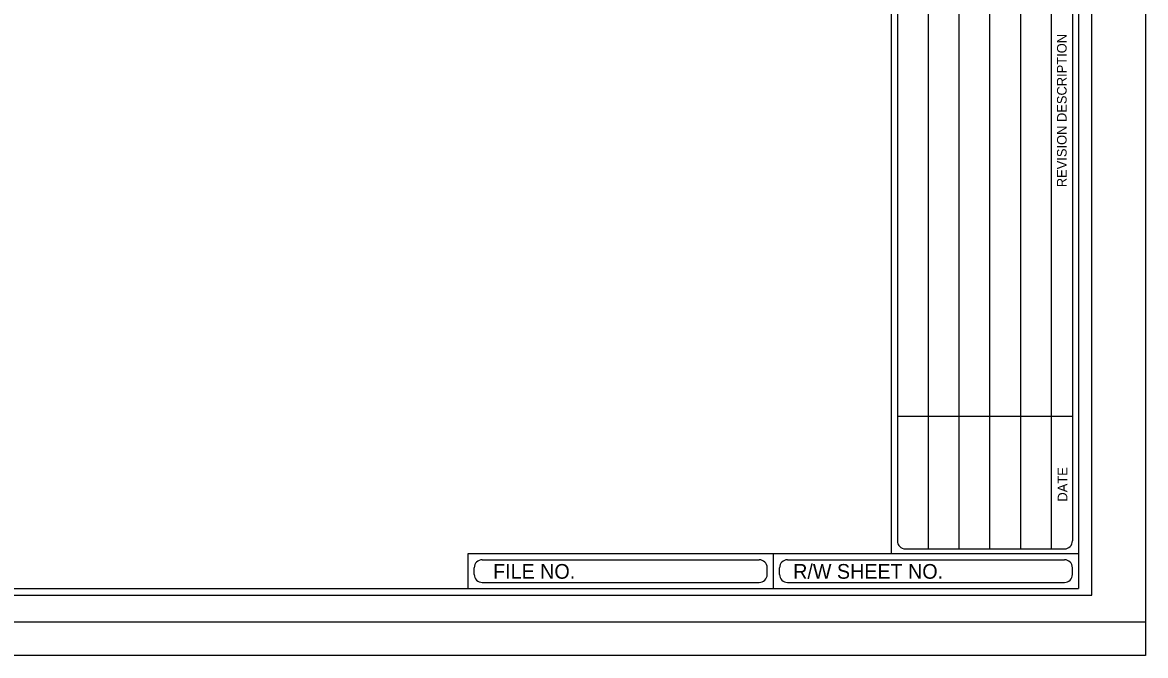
# Model space of a CAD drawing. Extents: x -2.5 to 31.7, y -0.7 to 21.7.
# Drawn here: x 23.31 to 31.7, y -0.5 to 4.23 of the extents above; entities that cross this region are included whole.
import ezdxf

# ---------------------------------------------------------------- set-up
doc = ezdxf.new("R2010")
doc.units = 0
for name, color, linetype in [('Plot Border', 7, 'Continuous'), ('Plot Border 2', 7, 'Continuous'), ('Sheet Border', 7, 'Continuous')]:
    doc.layers.add(name, color=color, linetype=linetype)

msp = doc.modelspace()

# ---------------------------------------------------------------- linework, layer by layer
at = {"layer": 'Plot Border'}
for points in [[(-2.3, 21.5), (31.7, 21.5), (31.7, -0.5), (-2.3, -0.5)], [(31.3, 21.05), (-1.7, 21.05), (-1.7, -0.05), (31.3, -0.05)]]:
    msp.add_lwpolyline(points, close=True, dxfattribs=at)
at = {"layer": 'Plot Border 2'}
msp.add_lwpolyline([(-2.3, 21.25), (31.7, 21.25), (31.7, -0.25), (-2.3, -0.25)], close=True, dxfattribs=at)
at = {"layer": 'Sheet Border'}
for p, q in [((29.8, 21), (29.8, 0.262)), ((31.2, 21), (31.2, 0)), ((29.8462, 6.7956), (29.8462, 0.3565)), ((30.0761, 6.8546), (30.0761, 0.297)), ((30.3059, 6.8546), (30.3059, 0.297)), ((30.5357, 6.8546), (30.5357, 0.297)), ((30.7655, 6.8546), (30.7655, 0.297)), ((30.9953, 6.8546), (30.9953, 0.297)), ((31.1538, 6.7956), (31.1538, 0.3565)), ((29.8462, 1.2876), (31.1538, 1.2876)), ((26.64, 0), (26.64, 0.262)), ((28.92, 0), (28.92, 0.262)), ((29.9057, 0.297), (31.0944, 0.297)), ((26.746, 0.216), (28.814, 0.216)), ((29.026, 0.216), (31.094, 0.216)), ((26.686, 0.106), (26.686, 0.156)), ((28.874, 0.106), (28.874, 0.156)), ((28.966, 0.106), (28.966, 0.156)), ((31.154, 0.106), (31.154, 0.156)), ((-0.3, 0), (31.2, 0)), ((26.746, 0.046), (28.814, 0.046)), ((29.026, 0.046), (31.094, 0.046))]:
    msp.add_line(p, q, dxfattribs=at)
msp.add_lwpolyline([(26.64, 0.262), (31.2, 0.262)], dxfattribs=at)
for centre, radius, start, end in [((29.9055, 0.3565), 0.0594, 180, 270), ((31.0942, 0.3565), 0.0594, 270, 0), ((26.746, 0.156), 0.06, 90, 180), ((28.814, 0.156), 0.06, 0, 90), ((29.026, 0.156), 0.06, 90, 180), ((31.094, 0.156), 0.06, 0, 90), ((26.746, 0.106), 0.06, 180, 270), ((28.814, 0.106), 0.06, 270, 0), ((29.026, 0.106), 0.06, 180, 270), ((31.094, 0.106), 0.06, 270, 0)]:
    msp.add_arc(centre, radius, start, end, dxfattribs=at)

# ---------------------------------------------------------------- texts
for s, p in [('REVISION DESCRIPTION', (31.1105, 2.9991)), ('DATE', (31.1158, 0.6503))]:
    msp.add_text(s, height=0.072, rotation=90, dxfattribs=at).set_placement(p)
for s, p in [('FILE NO.', (26.8268, 0.0737)), ('R/W SHEET NO.', (29.0681, 0.0737))]:
    msp.add_text(s, height=0.11, dxfattribs=at).set_placement(p)

doc.saveas('drawing.dxf')
